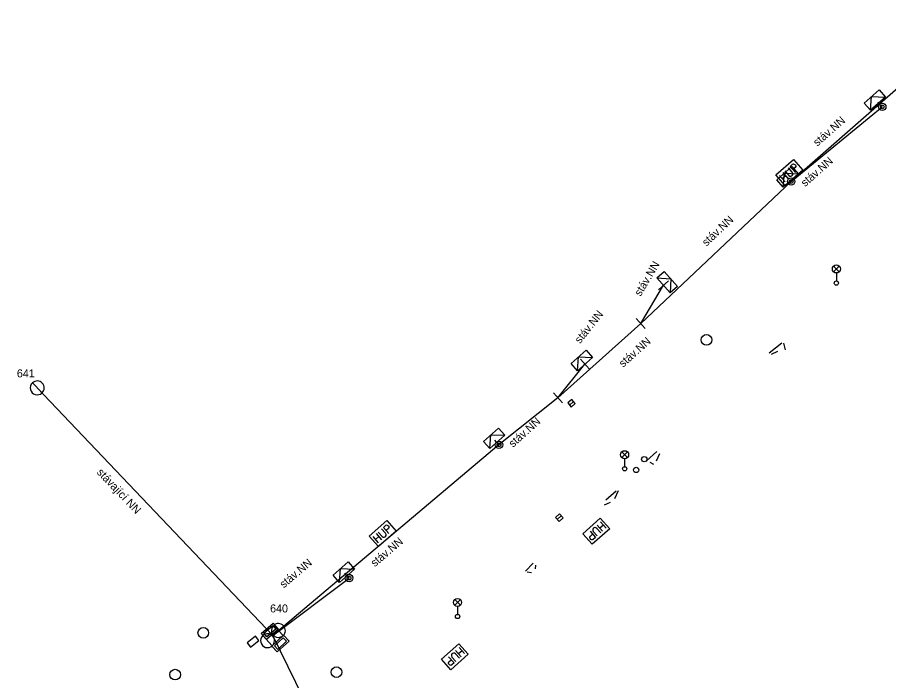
# Model space of a CAD drawing. Extents: x -584388 to -581645, y -1210859 to -1208922.
# Drawn here: x -582436 to -582354.4, y -1209703.5 to -1209641.4 of the extents above; entities that cross this region are included whole.
import ezdxf

# ---------------------------------------------------------------- set-up
doc = ezdxf.new("R2010")
doc.units = 0
for name, color, linetype in [('CIZÍ_NADZEM', 7, 'Continuous'), ('ELE_EON', 7, 'Continuous'), ('ELE_EON_POPIS', 7, 'Continuous')]:
    doc.layers.add(name, color=color, linetype=linetype)

msp = doc.modelspace()

# ---------------------------------------------------------------- linework, layer by layer
at = {"layer": 'CIZÍ_NADZEM'}
for p, q in [((-582359.524, -1209665.208), (-582358.996, -1209664.68)), ((-582358.988, -1209665.205), (-582359.516, -1209664.676)), ((-582359.26, -1209665.32), (-582359.26, -1209666.07)), ((-582384.271, -1209677.691), (-582383.889, -1209677.369)), ((-582379.364, -1209682.608), (-582378.836, -1209682.08)), ((-582378.828, -1209682.605), (-582379.356, -1209682.076)), ((-582379.1, -1209682.72), (-582379.1, -1209683.47)), ((-582385.043, -1209688.074), (-582385.417, -1209688.406)), ((-582395.024, -1209696.448), (-582394.496, -1209695.92)), ((-582394.488, -1209696.445), (-582395.016, -1209695.916)), ((-582394.76, -1209696.56), (-582394.76, -1209697.31))]:
    msp.add_line(p, q, dxfattribs=at)
for points in [[(-582364.928, -1209656.135), (-582363.276, -1209654.682), (-582362.404, -1209655.674), (-582364.056, -1209657.126), (-582364.928, -1209656.135)], [(-582364.085, -1209655.761), (-582363.721, -1209656.175), (-582363.626, -1209656.236), (-582363.527, -1209656.246), (-582363.433, -1209656.212), (-582363.385, -1209656.17), (-582363.34, -1209656.081), (-582363.341, -1209655.985), (-582363.389, -1209655.883), (-582363.753, -1209655.469)], [(-582363.59, -1209655.325), (-582363.375, -1209655.136), (-582363.281, -1209655.103), (-582363.233, -1209655.108), (-582363.162, -1209655.142), (-582363.089, -1209655.224), (-582363.064, -1209655.3), (-582363.066, -1209655.348), (-582363.111, -1209655.436), (-582363.325, -1209655.625)], [(-582363.081, -1209655.903), (-582363.59, -1209655.325)], [(-582364.581, -1209656.196), (-582364.072, -1209656.775)], [(-582364.341, -1209656.469), (-582364.009, -1209656.177)], [(-582363.741, -1209656.483), (-582364.249, -1209655.904)], [(-582380.5, -1209689.281), (-582382.14, -1209690.747), (-582383.02, -1209689.763), (-582381.38, -1209688.297), (-582380.5, -1209689.281)], [(-582403.048, -1209689.968), (-582401.399, -1209688.512), (-582400.525, -1209689.502), (-582402.175, -1209690.958), (-582403.048, -1209689.968)], [(-582401.712, -1209689.155), (-582401.497, -1209688.966), (-582401.404, -1209688.933), (-582401.355, -1209688.938), (-582401.284, -1209688.972), (-582401.212, -1209689.054), (-582401.187, -1209689.129), (-582401.188, -1209689.177), (-582401.233, -1209689.266), (-582401.447, -1209689.455)], [(-582401.202, -1209689.733), (-582401.712, -1209689.155)], [(-582381.69, -1209688.943), (-582381.177, -1209689.517)], [(-582381.089, -1209688.952), (-582381.419, -1209689.246)], [(-582380.847, -1209689.222), (-582381.361, -1209688.648)], [(-582401.86, -1209690.314), (-582402.37, -1209689.736)], [(-582402.206, -1209689.592), (-582401.841, -1209690.006), (-582401.746, -1209690.066), (-582401.647, -1209690.076), (-582401.553, -1209690.042), (-582401.506, -1209690.001), (-582401.461, -1209689.911), (-582401.462, -1209689.815), (-582401.51, -1209689.713), (-582401.875, -1209689.3)], [(-582381.831, -1209690.102), (-582382.044, -1209690.293), (-582382.138, -1209690.327), (-582382.186, -1209690.322), (-582382.257, -1209690.289), (-582382.331, -1209690.207), (-582382.356, -1209690.132), (-582382.355, -1209690.084), (-582382.311, -1209689.995), (-582382.098, -1209689.804)], [(-582382.345, -1209689.528), (-582381.831, -1209690.102)], [(-582381.339, -1209689.662), (-582381.707, -1209689.251), (-582381.802, -1209689.191), (-582381.902, -1209689.182), (-582381.996, -1209689.216), (-582382.043, -1209689.258), (-582382.087, -1209689.348), (-582382.086, -1209689.444), (-582382.037, -1209689.545), (-582381.669, -1209689.957)], [(-582402.701, -1209690.029), (-582402.192, -1209690.606)], [(-582402.461, -1209690.301), (-582402.13, -1209690.009)], [(-582393.751, -1209701.045), (-582395.394, -1209702.507), (-582396.272, -1209701.521), (-582394.628, -1209700.059), (-582393.751, -1209701.045)], [(-582394.098, -1209700.986), (-582394.61, -1209700.411)], [(-582395.596, -1209701.288), (-582395.084, -1209701.863)], [(-582394.591, -1209701.425), (-582394.958, -1209701.012), (-582395.053, -1209700.952), (-582395.152, -1209700.943), (-582395.246, -1209700.977), (-582395.293, -1209701.019), (-582395.338, -1209701.108), (-582395.337, -1209701.205), (-582395.288, -1209701.306), (-582394.921, -1209701.718)], [(-582394.94, -1209700.704), (-582394.428, -1209701.28)], [(-582394.339, -1209700.715), (-582394.669, -1209701.008)], [(-582395.084, -1209701.863), (-582395.298, -1209702.053), (-582395.391, -1209702.087), (-582395.44, -1209702.082), (-582395.511, -1209702.049), (-582395.584, -1209701.966), (-582395.609, -1209701.891), (-582395.608, -1209701.843), (-582395.564, -1209701.754), (-582395.35, -1209701.564)]]:
    msp.add_lwpolyline(points, dxfattribs=at)
for points in [[(-582384.109, -1209677.883), (-582383.727, -1209677.56), (-582384.05, -1209677.177), (-582384.433, -1209677.5)], [(-582385.209, -1209687.886), (-582385.584, -1209688.218), (-582385.252, -1209688.594), (-582384.877, -1209688.262)], [(-582413.684, -1209699.368), (-582414.479, -1209699.974), (-582414.176, -1209700.372), (-582413.381, -1209699.766)]]:
    msp.add_lwpolyline(points, close=True, dxfattribs=at)
for centre, radius in [((-582359.26, -1209664.945), 0.375), ((-582359.26, -1209666.27), 0.2), ((-582371.43, -1209671.59), 0.5), ((-582379.1, -1209682.345), 0.375), ((-582377.26, -1209682.77), 0.25), ((-582379.1, -1209683.67), 0.2), ((-582378.02, -1209683.78), 0.25), ((-582394.76, -1209696.185), 0.375), ((-582394.76, -1209697.51), 0.2), ((-582418.59, -1209699.04), 0.5), ((-582421.23, -1209702.96), 0.5), ((-582406.11, -1209702.73), 0.5)]:
    msp.add_circle(centre, radius, dxfattribs=at)
at = {"layer": 'ELE_EON'}
for p, q in [((-582355.192, -1209649.488), (-582355.358, -1209649.301)), ((-582363.721, -1209656.487), (-582363.886, -1209656.299)), ((-582375.919, -1209666.883), (-582374.981, -1209666.057)), ((-582378.006, -1209669.593), (-582377.174, -1209670.527)), ((-582383.236, -1209673.393), (-582382.404, -1209674.327)), ((-582433.702, -1209676.561), (-582434.598, -1209675.619)), ((-582385.766, -1209676.553), (-582384.934, -1209677.487)), ((-582391.112, -1209681.158), (-582391.279, -1209680.971)), ((-582405.162, -1209693.648), (-582405.327, -1209693.46)), ((-582411.993, -1209698.347), (-582411.105, -1209699.297)), ((-582413.015, -1209699.303), (-582412.127, -1209700.253))]:
    msp.add_line(p, q, dxfattribs=at)
for points in [[(-582345.95, -1209641.37), (-582363.49, -1209656.75), (-582363.54, -1209656.65)], [(-582356.062, -1209650.071), (-582355.957, -1209648.776), (-582354.658, -1209648.829)], [(-582363.49, -1209656.75), (-582354.96, -1209649.75), (-582355.36, -1209649.45)], [(-582364.244, -1209657.269), (-582364.134, -1209655.974), (-582362.836, -1209656.031)], [(-582363.49, -1209656.75), (-582377.59, -1209670.06)], [(-582376.07, -1209665.767), (-582374.775, -1209665.875), (-582374.83, -1209667.173)], [(-582377.59, -1209670.06), (-582375.45, -1209666.47)], [(-582377.59, -1209670.06), (-582385.35, -1209677.02)], [(-582365.55, -1209672.79), (-582364.36, -1209671.86)], [(-582364.01, -1209672.51), (-582364.19, -1209671.91)], [(-582364.77, -1209672.67), (-582365.37, -1209672.95)], [(-582383.52, -1209674.484), (-582383.419, -1209673.188), (-582382.12, -1209673.236)], [(-582385.35, -1209677.02), (-582382.82, -1209673.86)], [(-582412.06, -1209699.3), (-582434.15, -1209676.09)], [(-582385.35, -1209677.02), (-582390.88, -1209681.42), (-582391.04, -1209681.15)], [(-582391.741, -1209681.773), (-582391.638, -1209680.477), (-582390.339, -1209680.527)], [(-582390.88, -1209681.42), (-582412.06, -1209699.3)], [(-582377.04, -1209682.92), (-582376.08, -1209682.04)], [(-582376.13, -1209682.93), (-582375.79, -1209682.24)], [(-582376.37, -1209683.27), (-582376.71, -1209683.08)], [(-582380.87, -1209686.58), (-582379.88, -1209685.74)], [(-582380.01, -1209686.45), (-582379.69, -1209685.71)], [(-582380.45, -1209686.82), (-582381.02, -1209687.08)], [(-582405.833, -1209694.31), (-582405.726, -1209693.015), (-582404.427, -1209693.07)], [(-582388.4, -1209693.25), (-582387.66, -1209692.5)], [(-582387.46, -1209693.03), (-582387.42, -1209692.69)], [(-582412.06, -1209699.3), (-582404.93, -1209693.91), (-582405.13, -1209693.69)], [(-582387.83, -1209693.42), (-582388.24, -1209693.36)], [(-582389.99, -1209728.1), (-582406.33, -1209711.04), (-582412.06, -1209699.3)]]:
    msp.add_lwpolyline(points, dxfattribs=at)
for points in [[(-582356.659, -1209649.398), (-582355.255, -1209648.155), (-582354.658, -1209648.829), (-582356.062, -1209650.071)], [(-582364.838, -1209656.593), (-582363.43, -1209655.355), (-582362.836, -1209656.031), (-582364.244, -1209657.269)], [(-582375.395, -1209665.172), (-582374.155, -1209666.578), (-582374.83, -1209667.173), (-582376.07, -1209665.767)], [(-582384.119, -1209673.812), (-582382.719, -1209672.564), (-582382.12, -1209673.236), (-582383.52, -1209674.484)], [(-582392.339, -1209681.1), (-582390.937, -1209679.855), (-582390.339, -1209680.527), (-582391.741, -1209681.773)], [(-582406.428, -1209693.636), (-582405.023, -1209692.395), (-582404.427, -1209693.07), (-582405.833, -1209694.31)], [(-582411.542, -1209698.689), (-582412.679, -1209699.668), (-582413.168, -1209699.099), (-582412.032, -1209698.121)], [(-582411.792, -1209698.706), (-582412.625, -1209699.424), (-582412.919, -1209699.083), (-582412.085, -1209698.365)], [(-582410.556, -1209699.81), (-582411.652, -1209700.835), (-582412.164, -1209700.287), (-582411.068, -1209699.263)], [(-582410.805, -1209699.837), (-582411.608, -1209700.589), (-582411.915, -1209700.26), (-582411.112, -1209699.509)]]:
    msp.add_lwpolyline(points, close=True, dxfattribs=at)
for centre, radius in [((-582354.96, -1209649.75), 0.35), ((-582354.96, -1209649.75), 0.175), ((-582363.49, -1209656.75), 0.35), ((-582363.49, -1209656.75), 0.175), ((-582390.88, -1209681.42), 0.35), ((-582390.88, -1209681.42), 0.175), ((-582404.93, -1209693.91), 0.35), ((-582404.93, -1209693.91), 0.175)]:
    msp.add_circle(centre, radius, dxfattribs=at)
for centre, start, end in [((-582434.15, -1209676.09), 133.5837, 313.5837), ((-582434.15, -1209676.09), 313.5837, 133.5837), ((-582411.549, -1209698.822), 133.07804, 313.07804), ((-582411.549, -1209698.822), 313.07804, 133.07804), ((-582412.571, -1209699.778), 133.07804, 313.07804), ((-582412.571, -1209699.778), 313.07804, 133.07804)]:
    msp.add_arc(centre, 0.65, start, end, dxfattribs=at)

# ---------------------------------------------------------------- texts
at = {"layer": 'ELE_EON_POPIS'}
for s, rotation, p in [('stáv.NN', 41.24597, (-582361.04, -1209653.49)), ('stáv.NN', 41.24597, (-582362.19, -1209657.28)), ('stáv.NN', 43.34913, (-582371.43, -1209662.86)), ('stáv.NN', 59.20081, (-582377.61, -1209667.56)), ('stáv.NN', 51.31811, (-582383.28, -1209671.99)), ('stáv.NN', 41.88917, (-582379.24, -1209674.2)), ('stáv.NN', 41.88917, (-582389.57, -1209681.71)), ('stávající NN', 313.5837, (-582428.62, -1209684.05)), ('stáv.NN', 40.17082, (-582402.52, -1209692.9)), ('stáv.NN', 40.17082, (-582411.05, -1209694.89))]:
    msp.add_text(s, height=0.75, rotation=rotation, dxfattribs=at).set_placement(p)
for s, p in [('641', (-582436.06, -1209675.1)), ('640', (-582412.33, -1209697.13))]:
    msp.add_text(s, height=0.75, dxfattribs=at).set_placement(p)

doc.saveas('drawing.dxf')
